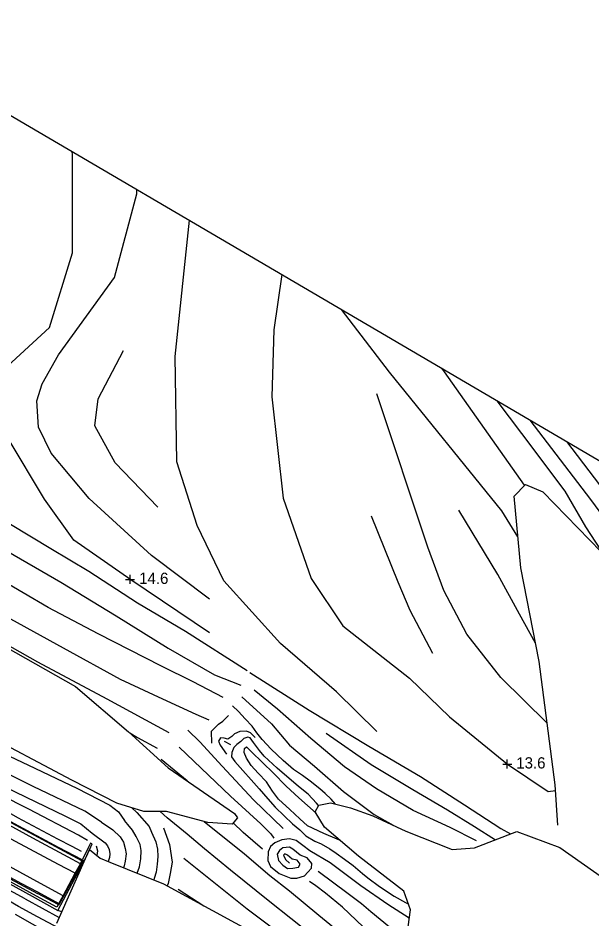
# Model space of a CAD drawing. Extents: x 2316231 to 2323598, y 363169 to 371906.
# Drawn here: x 2318517.1 to 2318772.4, y 366976.9 to 367377.9 of the extents above; entities that cross this region are included whole.
import ezdxf

# ---------------------------------------------------------------- set-up
doc = ezdxf.new("R2010")
doc.units = 0
for name, color, linetype in [('RD_DTM_BkLn1', 7, 'Continuous'), ('RD_DTM_BkLn2', 7, 'Continuous'), ('RD_DTM_Holes', 7, 'Continuous'), ('RD_DTM_TinHull', 7, 'Continuous'), ('RD_DTM_Void', 7, 'Continuous'), ('RD_EX_BldgApp', 7, 'Continuous'), ('RD_EX_Road', 7, 'Continuous')]:
    doc.layers.add(name, color=color, linetype=linetype)

msp = doc.modelspace()

# ---------------------------------------------------------------- linework, layer by layer
at = {"layer": 'RD_DTM_BkLn1'}
for p, q in [((2318611.731, 367054.477), (2318608.895, 367055.877)), ((2318542.594, 366997.35), (2318535.171, 367001.222)), ((2318517.307, 366982.525), (2318495.318, 366995.157)), ((2318537.166, 366987.262), (2318527.129, 366992.672)), ((2318588.3, 366990.227), (2318599.83, 366982.772)), ((2318520.274, 366985.87), (2318535.437, 366977.575)), ((2318536.565, 366980.103), (2318534.778, 366980.752))]:
    msp.add_line(p, q, dxfattribs=at)
for points in [[(2318531.113, 367240.202), (2318541.262, 367273.344), (2318541.345, 367317.024), (2318541.215, 367318.461)], [(2318602.224, 367119.201), (2318576.506, 367138.614), (2318548.823, 367164.089), (2318531.894, 367184.184), (2318526.152, 367195.771), (2318525.423, 367207.45), (2318527.816, 367215.015), (2318535.142, 367227.961), (2318560.062, 367262.466), (2318569.945, 367299.577), (2318569.977, 367301.587)], [(2318676.765, 367060.366), (2318658.777, 367078.019), (2318633.795, 367099.522), (2318608.656, 367127.429), (2318596.759, 367151.981), (2318587.774, 367180.431), (2318587.017, 367227.178), (2318593.326, 367287.889)], [(2318634.481, 367263.745), (2318630.89, 367239.15), (2318629.987, 367209.283), (2318635.055, 367164.172), (2318647.547, 367128.396), (2318661.529, 367107.389), (2318691.195, 367084.141), (2318709.096, 367066.94), (2318734.868, 367045.788), (2318752.882, 367033.601), (2318756.156, 367034.104)], [(2318739.44, 367147.022), (2318732.319, 367158.624), (2318682.319, 367220.304), (2318660.994, 367248.19)], [(2318579.229, 367160.261), (2318560.287, 367180), (2318551.3, 367196.337), (2318552.788, 367208.444), (2318564.062, 367229.968)], [(2318742.456, 367169.944), (2318706.882, 367220.364), (2318705.623, 367222.008)], [(2318752.477, 367064.013), (2318731.864, 367084.347), (2318716.737, 367103.706), (2318706.467, 367123.131), (2318699.365, 367142.329), (2318676.768, 367210.688)], [(2318777.453, 367139.112), (2318776.379, 367141.273), (2318769.683, 367151.513), (2318760.518, 367167.357), (2318741.169, 367193.032), (2318730.264, 367207.552)], [(2318988.503, 366875.142), (2318959.408, 366913.365), (2318939.826, 366937.347), (2318912.393, 366975.332), (2318887.881, 367008.663), (2318860.276, 367044.788), (2318829.928, 367086.131), (2318798.694, 367127.123), (2318771.89, 367163.635), (2318744.974, 367198.922)], [(2318993.227, 366880.13), (2318947.131, 366943.061), (2318914.193, 366987.309), (2318882.196, 367030.229), (2318856.726, 367063.172), (2318824.995, 367105.541), (2318793.351, 367147.072), (2318761.246, 367189.376)], [(2318619.1, 367087.356), (2318591.646, 367104.82), (2318570.297, 367117.406), (2318548.601, 367131.496), (2318531.712, 367141.687), (2318504.224, 367158.06), (2318481.222, 367172.988), (2318470.33, 367179.235)], [(2318464.381, 367171.33), (2318492.062, 367153.119), (2318509.827, 367142.064), (2318536.173, 367126.783), (2318560.728, 367111.822), (2318583.818, 367097.436), (2318604.435, 367085.652), (2318616.154, 367080.923)], [(2318608.345, 367075.536), (2318595.039, 367082.533), (2318580.865, 367089.496), (2318552.7, 367103.876), (2318530.463, 367115.62), (2318508.058, 367128.544), (2318487.838, 367139.562), (2318454.975, 367160.488)], [(2318747.339, 367099.633), (2318740.138, 367112.576), (2318730.463, 367130.289), (2318713.165, 367158.898)], [(2318701.623, 367095.024), (2318691.571, 367114.138), (2318686.136, 367126.782), (2318674.281, 367156.144)], [(2318446.568, 367151.71), (2318483.679, 367128.23), (2318503.333, 367116.146), (2318537.169, 367097.566), (2318562.51, 367083.619), (2318581.366, 367074.965), (2318596.25, 367068.114), (2318602.039, 367065.605)], [(2318584.275, 367059.812), (2318556.717, 367074.816), (2318525.977, 367091.255), (2318503.258, 367103.924), (2318481.051, 367117.155), (2318460.801, 367128.2), (2318436.543, 367142.743)], [(2318387.848, 367113.286), (2318415.173, 367099.467), (2318443.643, 367085.229), (2318472.945, 367069.26), (2318498.795, 367056.243), (2318521.722, 367045.318), (2318543.308, 367035.207), (2318557.903, 367027.577), (2318561.766, 367024.616), (2318564.451, 367020.684)], [(2318554.272, 367019.973), (2318546.843, 367024.932), (2318523.772, 367035.921), (2318491.867, 367051.838), (2318458.052, 367070.589), (2318424.018, 367087.97), (2318384.165, 367108.971)], [(2318380.265, 367104.299), (2318408.564, 367089.189), (2318440.483, 367072.529), (2318473.61, 367055.296), (2318500.966, 367040.679), (2318520.491, 367031.335), (2318538.222, 367022.664), (2318545.031, 367019.226), (2318550.059, 367015.076)], [(2318548.002, 367011.912), (2318543.954, 367014.284), (2318521.857, 367025.779), (2318496.499, 367038.579), (2318471.103, 367052.778), (2318439.548, 367068.931), (2318411.058, 367083.742), (2318378.731, 367100.8)], [(2318375.7, 367097.691), (2318413.06, 367077.904), (2318449.428, 367058.007), (2318477.056, 367043.913), (2318501.485, 367030.864), (2318516.944, 367022.043), (2318534.624, 367012.648), (2318541.029, 367009.375), (2318545.185, 367007.107)], [(2318535.171, 367001.222), (2318516.022, 367011.403), (2318496.796, 367021.624), (2318477.812, 367031.787), (2318457.234, 367042.752), (2318434.751, 367054.774), (2318415.703, 367065.103), (2318398.489, 367074.372), (2318382.105, 367083.29), (2318368.321, 367090.682)], [(2318620.255, 367086.62), (2318646.598, 367069.813), (2318673.135, 367053.889), (2318696.114, 367040.354), (2318715.722, 367027.741), (2318731.9, 367017.264), (2318736.154, 367014.796)], [(2318527.129, 366992.672), (2318505.577, 367004.426), (2318484.729, 367015.704), (2318463.029, 367027.473), (2318437.754, 367041.225), (2318420.102, 367050.756), (2318400.588, 367061.226), (2318381.169, 367071.757), (2318363.095, 367081.552), (2318360.095, 367083.173)], [(2318721.002, 367011.78), (2318709.264, 367017.594), (2318692.911, 367025.274), (2318676.545, 367034.783), (2318662.403, 367044.68), (2318647.386, 367057.213), (2318632.556, 367070.373), (2318622.095, 367078.707)], [(2318616.717, 367075.839), (2318629.922, 367063.841), (2318637.921, 367054.341), (2318649.045, 367044.885), (2318661.882, 367033.63), (2318675.553, 367023.424), (2318683.907, 367018.628)], [(2318658.32, 367028.023), (2318656.465, 367030.298), (2318653.661, 367032.743), (2318651.381, 367034.878), (2318647.12, 367038.187), (2318643.691, 367040.807), (2318639.683, 367043.484), (2318635.099, 367047.418), (2318629.737, 367052.507), (2318625.639, 367056.752), (2318623.274, 367059.795), (2318621.302, 367062.73), (2318618.196, 367066.058), (2318615.135, 367069.284), (2318612.466, 367071.811)], [(2318603.298, 367055.184), (2318603.229, 367060.528), (2318606.332, 367063.615), (2318608.241, 367064.961), (2318610.705, 367067.462)], [(2318566.853, 367059.71), (2318570.28, 367057.701), (2318579.036, 367052.911)], [(2318635.029, 367017.182), (2318621.791, 367029.901), (2318607.942, 367044.981), (2318597.934, 367055.759), (2318592.707, 367061.009)], [(2318622.576, 367057.728), (2318620.456, 367059.806), (2318618.671, 367060.528), (2318615.821, 367060.329), (2318613.39, 367059.279), (2318612.145, 367058.145), (2318610.41, 367056.927), (2318608.766, 367057.398), (2318607.18, 367057.612), (2318606.277, 367056.124), (2318607.082, 367054.24), (2318609.898, 367050.306)], [(2318654.139, 367059.586), (2318674.25, 367045.646), (2318692.775, 367034.523), (2318708.219, 367025.503), (2318720.163, 367018.103), (2318729.488, 367012.226)], [(2318650.832, 367027.365), (2318649.852, 367028.447), (2318646.152, 367032.421), (2318641.925, 367035.924), (2318632.406, 367044.026), (2318626.528, 367049.341), (2318624.563, 367051.85), (2318621.876, 367055.519), (2318620.438, 367057.583), (2318619.311, 367057.906), (2318617.563, 367057.262), (2318616.222, 367055.921), (2318614.422, 367054.548), (2318613.087, 367053.215), (2318612.28, 367051.004), (2318612.099, 367049.115), (2318613.497, 367047.019), (2318624.394, 367034.783), (2318628.241, 367030.411), (2318631.541, 367026.709), (2318635.459, 367022.839), (2318639.268, 367019.336), (2318642.453, 367016.582), (2318645.191, 367013.982), (2318649.097, 367011.601), (2318651.889, 367010.304), (2318655.775, 367008.149), (2318658.624, 367006.176), (2318662.363, 367003.504), (2318666.121, 367000.685), (2318670.316, 366997.144), (2318672.662, 366995.241), (2318677.908, 366991.441), (2318684.439, 366987.054), (2318689.447, 366984.305), (2318690.724, 366983.689)], [(2318520.274, 366985.87), (2318492.329, 367001.055), (2318461.733, 367017.727), (2318428.77, 367036.285), (2318401.152, 367051.519)], [(2318588.758, 367053.416), (2318611.606, 367031.524), (2318625.139, 367019.249), (2318629.489, 367014.883), (2318630.952, 367012.942)], [(2318660.462, 367011.835), (2318659.046, 367012.442), (2318653.097, 367014.99), (2318645.889, 367018.405), (2318642.487, 367021.552), (2318638.007, 367025.687), (2318633.039, 367030.234), (2318630.255, 367033.788), (2318627.677, 367038.006), (2318623.914, 367041.811), (2318620.834, 367045.262), (2318618.688, 367048.487), (2318617.741, 367051.039), (2318617.825, 367052.813), (2318618.709, 367053.612), (2318620.843, 367051.536), (2318626.049, 367046.355), (2318630.548, 367041.995), (2318636.406, 367035.99), (2318642.013, 367030.773), (2318649.718, 367023.986)], [(2318592.464, 367038.3), (2318592.401, 367038.353), (2318580.704, 367047.952)], [(2318567.774, 367026.404), (2318569.932, 367024.263), (2318575.468, 367018.046), (2318576.493, 367015.493), (2318578.341, 367011.249), (2318579.184, 367007.999), (2318579.344, 367004.763), (2318579.065, 367001.255), (2318578.522, 366997.775), (2318577.728, 366994.99), (2318577.45, 366994.338)], [(2318691.746, 366934.2), (2318681.264, 366942.831), (2318675.109, 366947.896), (2318669.952, 366951.817), (2318647.832, 366969.718), (2318629.154, 366984.504), (2318611.668, 366998.702), (2318600.126, 367008.158), (2318592.385, 367014.693), (2318583.387, 367022.001), (2318580.263, 367024.719)], [(2318554.272, 367019.973), (2318559.215, 367016.651), (2318562.501, 367013.445), (2318564.01, 367011.046), (2318564.769, 367008.364), (2318565.168, 367005.907), (2318564.793, 367002.703), (2318564.359, 367000.53), (2318564.053, 366999.763)], [(2318570.102, 366997.314), (2318571.084, 367000.141), (2318571.775, 367003.719), (2318571.887, 367007.432), (2318571.392, 367010.101), (2318569.722, 367013.565), (2318568.099, 367016.48), (2318565.947, 367018.937), (2318564.451, 367020.684)], [(2318599.87, 367020.364), (2318617.893, 367005.906), (2318629.115, 366996.224), (2318637.874, 366989.392), (2318650.983, 366978.614), (2318661.586, 366969.873), (2318666.348, 366965.996), (2318672.387, 366960.964), (2318679.303, 366955.205), (2318685.992, 366949.27), (2318691.858, 366945.444), (2318695.622, 366944.307)], [(2318625.895, 367008.037), (2318617.24, 367015.487), (2318612.877, 367019.756)], [(2318550.059, 367015.076), (2318555.886, 367010.863), (2318556.955, 367009.463), (2318557.67, 367007.799), (2318557.946, 367005.878), (2318557.811, 367004.292), (2318557.217, 367002.526)], [(2318581.784, 367017.451), (2318584.546, 367010.042), (2318585.633, 367002.215), (2318584.838, 366997.102), (2318583.837, 366992.738), (2318583.398, 366991.711)], [(2318691.132, 366977.296), (2318681.622, 366983.346), (2318669.577, 366991.617), (2318656.008, 367001.867), (2318646.836, 367007.28), (2318643.73, 367009.693), (2318640.79, 367011.9), (2318637.818, 367012.642), (2318634.421, 367012.199), (2318631.357, 367010.833), (2318629.475, 367009.176), (2318628.345, 367006.753), (2318628.157, 367003.026), (2318629.342, 367000.337), (2318633.325, 366997.119), (2318638.494, 366995.15), (2318641.176, 366995.072), (2318644.569, 366996.16), (2318646.026, 366997.809), (2318647.606, 366999.511), (2318647.807, 367001.671), (2318645.72, 367004.205), (2318642.607, 367005.354), (2318639.403, 367007.993), (2318637.798, 367008.851), (2318634.909, 367008.607), (2318633.406, 367007.415), (2318632.425, 367005.835), (2318633.018, 367003.018), (2318634.913, 367000.922), (2318636.917, 366999.374), (2318639.354, 366999.502), (2318641.83, 367000.016), (2318642.676, 367001.344), (2318641.232, 367003.06), (2318639.046, 367003.57), (2318636.952, 367005.338), (2318635.831, 367005.931), (2318635.191, 367005.267), (2318636.067, 367003.468), (2318637.859, 367001.824)], [(2318551.826, 367009.527), (2318552.509, 367007.328), (2318552.146, 367005.239), (2318552.133, 367005.198)], [(2318534.955, 366983.312), (2318535.262, 366983.765), (2318537.166, 366987.262), (2318542.594, 366997.35), (2318544.874, 367001.524), (2318545.53, 367002.828), (2318545.661, 367003.223)], [(2318590.869, 367003.998), (2318619.086, 366981.382), (2318648.096, 366959.707), (2318666.241, 366946.444)], [(2318650.578, 366998.194), (2318663.926, 366988.195), (2318669.843, 366983.841), (2318674.038, 366980.299), (2318682.34, 366973.422), (2318689.32, 366968.59), (2318692.059, 366966.562)], [(2318697.067, 366952.905), (2318686.073, 366961.83), (2318673.685, 366970.455), (2318661.376, 366982.181), (2318653.847, 366988.471), (2318649.556, 366991.728), (2318646.804, 366993.553)], [(2318574.81, 366950.203), (2318566.05, 366955.406), (2318540.023, 366970.337), (2318525.81, 366977.886), (2318517.307, 366982.525)], [(2318515.815, 366979.099), (2318539.554, 366965.55), (2318562.424, 366952.801), (2318589.691, 366936.903), (2318621.365, 366917.716), (2318649.777, 366900.432), (2318656.326, 366897.268)]]:
    msp.add_lwpolyline(points, dxfattribs=at)
at = {"layer": 'RD_DTM_BkLn2'}
for p, q in [((2318544.874, 367001.524), (2318539.431, 367004.378)), ((2318525.695, 366989.067), (2318535.262, 366983.765))]:
    msp.add_line(p, q, dxfattribs=at)
for points in [[(2318539.431, 367004.378), (2318523.69, 367012.89), (2318504.067, 367023.553), (2318488.335, 367032.162), (2318470.748, 367041.676), (2318452.632, 367051.468), (2318433.858, 367061.683), (2318415.4, 367071.679), (2318395.722, 367082.297), (2318373.346, 367094.452)], [(2318358.839, 367079.341), (2318378.663, 367068.616), (2318398.885, 367057.705), (2318416.827, 367048.004), (2318434.893, 367038.081), (2318450.304, 367029.817), (2318471.22, 367018.451), (2318485.119, 367010.887), (2318500.923, 367002.401), (2318518.398, 366992.841), (2318525.695, 366989.067)]]:
    msp.add_lwpolyline(points, dxfattribs=at)
at = {"layer": 'RD_DTM_Holes'}
for points in [[(2318757.221, 367018.714), (2318755.976, 367036.695), (2318748.963, 367091.442), (2318740.694, 367133.135), (2318737.811, 367165.062), (2318742.828, 367170.335), (2318750.541, 367166.971), (2318776.49, 367140.326), (2318808.55, 367099.877), (2318843.276, 367055.384), (2318862.143, 367024.13), (2318896.12, 366984.036), (2318929.401, 366943.999), (2318942.563, 366924.141), (2318952.973, 366908.758), (2318955.243, 366898.764), (2318950.067, 366891.32)], [(2318506.982, 367100.617), (2318542.675, 367080.319), (2318566.259, 367060.251), (2318583.84, 367044.253), (2318613.445, 367023.818), (2318614.692, 367021.993), (2318612.364, 367019.123), (2318601.594, 367019.918), (2318583.091, 367024.709), (2318573.009, 367024.743), (2318561.079, 367028.527), (2318541.017, 367038.752), (2318498.911, 367060.991)], [(2318690.595, 366973.403), (2318691.642, 366980.999), (2318688.794, 366989.345), (2318668.613, 367004.955), (2318653.429, 367017.772), (2318649.33, 367024.635), (2318650.923, 367027.53), (2318656.043, 367028.573), (2318664.968, 367026.418), (2318674.923, 367022.817), (2318689.572, 367015.986), (2318710.18, 367007.921), (2318720.086, 367008.602), (2318738.944, 367015.872), (2318758.094, 367008.749), (2318788.064, 366987.639)], [(2318534.304, 366975.034), (2318548.957, 367007.879), (2318553.58, 367003.977), (2318558.015, 367002.208), (2318581.822, 366992.568), (2318635.488, 366963.374)]]:
    msp.add_lwpolyline(points, dxfattribs=at)
at = {"layer": 'RD_DTM_TinHull'}
msp.add_lwpolyline([(2318895.931, 366251.828), (2318692.475, 366476.056), (2318535.868, 366505.408), (2318294.531, 366648.197), (2318021.792, 366800.778), (2317786.222, 367015.278), (2317543.269, 367137.281), (2317395.794, 367447.607), (2317668.048, 367803.596), (2318009.783, 367630.234), (2318999.407, 367049.655)], dxfattribs=at)
at = {"layer": 'RD_DTM_Void'}
for p, q in [((2318564.974, 367128.042), (2318568.974, 367128.042)), ((2318566.974, 367126.042), (2318566.974, 367130.042)), ((2318734.736, 367043.897), (2318734.736, 367047.897)), ((2318732.736, 367045.897), (2318736.736, 367045.897))]:
    msp.add_line(p, q, dxfattribs=at)
at = {"layer": 'RD_EX_BldgApp'}
msp.add_lwpolyline([(2318494.148, 367003.158), (2318523.416, 366987.065), (2318534.764, 366980.757), (2318547.564, 367004.71), (2318548.835, 367007.72), (2318550.062, 367010.414), (2318549.353, 367010.659), (2318548.638, 367009.13), (2318547.689, 367007.261), (2318545.666, 367003.237), (2318546.033, 367003.176), (2318535.262, 366983.176), (2318534.946, 366983.299), (2318534.333, 366982.246), (2318525.305, 366987.132), (2318500.101, 367000.919)], dxfattribs=at)
at = {"layer": 'RD_EX_Road'}
for p, q in [((2318545.653, 367003.244), (2318535.056, 367008.713)), ((2318545.53, 367002.828), (2318537.717, 367007.029)), ((2318534.933, 366983.306), (2318525.752, 366988.312))]:
    msp.add_line(p, q, dxfattribs=at)
for points in [[(2318531.113, 367240.202), (2318510.641, 367221.245), (2318485.644, 367197.425), (2318476.842, 367188.492)], [(2318602.294, 367104.293), (2318567.241, 367127.856), (2318541.975, 367145.46), (2318528.867, 367163.771), (2318512.763, 367190.754), (2318509.353, 367207.124), (2318512.817, 367219.958)], [(2318535.056, 367008.713), (2318515.508, 367019.321), (2318499.635, 367027.91), (2318481.414, 367037.974), (2318463.527, 367047.544), (2318445.04, 367057.538), (2318426.015, 367067.833), (2318407.922, 367077.577), (2318389.678, 367087.378), (2318373.809, 367095.896)], [(2318537.717, 367007.029), (2318524.271, 367014.213), (2318510.156, 367021.73), (2318496.766, 367029.006), (2318481.593, 367037.175), (2318465.282, 367046.055), (2318449.46, 367054.639), (2318433.837, 367063.041), (2318419.579, 367070.864), (2318403.587, 367079.454), (2318388.414, 367087.623), (2318373.969, 367095.507)], [(2318359.358, 367078.544), (2318387.946, 367063.009), (2318412.812, 367049.535), (2318432.761, 367038.561), (2318453.412, 367027.557), (2318472.363, 367017.181), (2318492.731, 367006.178), (2318511.642, 366995.906), (2318525.752, 366988.312)]]:
    msp.add_lwpolyline(points, dxfattribs=at)

# ---------------------------------------------------------------- texts
at = {"layer": 'RD_DTM_Void'}
for s, p in [('14.6', (2318570.974, 367126.042)), ('13.6', (2318738.736, 367043.897))]:
    msp.add_text(s, height=5, dxfattribs=at).set_placement(p)

doc.saveas('drawing.dxf')
